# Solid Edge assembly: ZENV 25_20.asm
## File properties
Title: Zylinder
Author: bmolnar
Template: iso metric assembly.asm
Last saved by: bmolnar
Revision: 12
Application: Solid Edge
Username: bmolnar
Dokumentum tartalom típus: 1
Document Number: ZENV 25/20
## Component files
Kit_1.par
Kit_2.par
Profilrohr.par
Kolbenstange.par
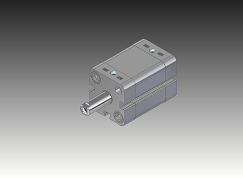
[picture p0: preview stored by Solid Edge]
